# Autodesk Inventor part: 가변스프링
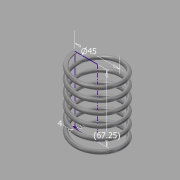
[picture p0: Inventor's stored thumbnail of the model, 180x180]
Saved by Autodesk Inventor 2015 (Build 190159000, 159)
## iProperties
Created: 2016-02
Part Number: 가변스프링
Material: 스테인레스 스틸
Document SubType Name: Modeling
Designer: Administrator
Mass: 84.1995 g
Surface Area: 106.448 cm^2
Volume: 10.5249 cm^3
Density: 8 g/cm^3
Appearance: 반연마
Author: Administrator
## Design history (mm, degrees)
sketch "스케치1"
  geometry: L1 (0, 0)-(22.5, 0); L2 (22.5, 0)-(22.5, 67.25); L3 (22.5, 67.25)-(0, 67.25); L4 (0, 67.25)-(0, 0); C1 r 2 at (22.5, 0)
  constraints: 8 end point, 3 perpendicular, 1 centre point, 1 coincident, 1 horizontal
  dimensions: "d0" = 45 diameter of L2 L4; "d1" = 67.25 distance between parallel lines of L1 L3 (derived); "d2" = 4 diameter of C1
feature "코일1" sketch "스케치1" pitch "d3" = 10; turns "d5" = 6; dims "d4" = 67.25 (= d1), "d6" = 0, angle "d7" = 90 deg, angle "d8" = 90 deg, "d9" = 0, "d10" = 0
sketch "스케치3"
  geometry: L1 (-20.5, 0)-(-24.5, 0) reference; 1 further point
  constraints: 1 horizontal alignment
extrude "돌출1" cut sketch "스케치3" stored distance "d11" = 10; taper "d12" = 0 deg
node "작업 평면1"
sketch "스케치4"
  geometry: L1 (20.5, 0)-(24.5, 0) reference; 1 further point
  constraints: 1 horizontal alignment
extrude "돌출2" cut sketch "스케치4" stored distance "d13" = 10; taper "d14" = 0 deg
node "솔리드1"
node "절단 모서리 투영2"
node "절단 모서리 투영3"
